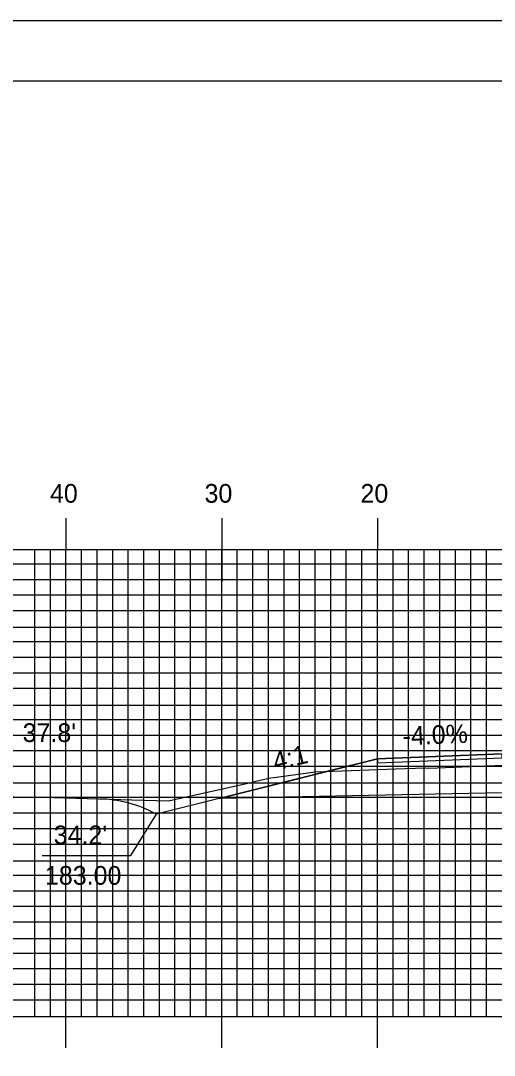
# Model space of a CAD drawing. Extents: x 1823966 to 1824309, y 442591 to 442811.
# Drawn here: x 1824088.9 to 1824119.3, y 442744.1 to 442810.5 of the extents above; entities that cross this region are included whole.
import ezdxf

# ---------------------------------------------------------------- set-up
doc = ezdxf.new("R2010")
doc.units = 0
for name, color, linetype in [('ANNOTATION', 7, 'Continuous'), ('BORDER', 7, 'Continuous'), ('D_Roadway_Centerline', 7, 'Continuous'), ('D_Roadway_Edge_Shoulder', 7, 'Continuous'), ('D_Roadway_SlopeLines', 7, 'Continuous'), ('D_Roadway_SubGrade', 7, 'Continuous'), ('D_Text_Standard', 7, 'Continuous'), ('H_V ANNOTATION', 7, 'Continuous'), ('MAJOR', 7, 'Continuous'), ('MINOR', 7, 'Continuous'), ('PLOT BOUNDARY', 7, 'Continuous'), ('S_Roadway_Centerline', 7, 'Continuous')]:
    doc.layers.add(name, color=color, linetype=linetype)

msp = doc.modelspace()

# ---------------------------------------------------------------- linework, layer by layer
at = {"layer": 'ANNOTATION'}
msp.add_lwpolyline([(1824090.301, 442756.925), (1824095.992, 442756.925), (1824097.632, 442759.588)], dxfattribs=at)
at = {"layer": 'BORDER'}
msp.add_lwpolyline([(1823982.222, 442596.665), (1824302.222, 442596.665), (1824302.222, 442806.665), (1823982.222, 442806.665)], close=True, dxfattribs=at)
at = {"layer": 'D_Roadway_Centerline'}
msp.add_lwpolyline([(1824101.648, 442760.592), (1824108.628, 442762.337), (1824111.822, 442763.135), (1824119.822, 442763.455), (1824131.822, 442763.695), (1824143.822, 442763.455), (1824151.822, 442763.135), (1824157.822, 442763.255), (1824158.422, 442763.301), (1824167.853, 442762.587), (1824172.409, 442763.689), (1824176.965, 442764.792), (1824176.965, 442764.792), (1824178.215, 442765.061), (1824179.465, 442765.188)], dxfattribs=at)
at = {"layer": 'D_Roadway_Edge_Shoulder'}
msp.add_lwpolyline([(1824119.822, 442763.455), (1824111.822, 442763.135), (1824111.822, 442762.885), (1824119.822, 442763.205)], close=True, dxfattribs=at)
at = {"layer": 'D_Roadway_SlopeLines'}
for p, q in [((1824111.822, 442763.135), (1824097.632, 442759.588)), ((1824097.632, 442759.588), (1824097.366, 442759.72))]:
    msp.add_line(p, q, dxfattribs=at)
msp.add_lwpolyline([(1824111.822, 442763.135), (1824108.628, 442762.337)], dxfattribs=at)
msp.add_arc((1824093.788, 442752.565), 8, 63.43495, 88.37605, dxfattribs=at)
at = {"layer": 'D_Roadway_SubGrade'}
msp.add_lwpolyline([(1824119.822, 442760.955), (1824101.648, 442760.592), (1824111.822, 442763.135), (1824111.822, 442762.885), (1824119.822, 442763.205), (1824131.822, 442763.445), (1824143.822, 442763.205), (1824151.822, 442762.885), (1824151.822, 442763.135), (1824151.822, 442760.635), (1824143.822, 442760.955), (1824131.822, 442761.195)], close=True, dxfattribs=at)
at = {"layer": 'MAJOR'}
for p, q in [((1824091.822, 442778.592), (1824091.822, 442776.588)), ((1824101.822, 442778.592), (1824101.822, 442776.588)), ((1824111.822, 442778.592), (1824111.822, 442776.588)), ((1823991.822, 442776.588), (1824271.822, 442776.588)), ((1824091.822, 442746.588), (1824091.822, 442776.588)), ((1824101.822, 442746.588), (1824101.822, 442776.588)), ((1824111.822, 442746.588), (1824111.822, 442776.588)), ((1824101.822, 442776.514), (1824101.822, 442774.51)), ((1823991.822, 442771.588), (1824271.822, 442771.588)), ((1823991.822, 442766.588), (1824271.822, 442766.588)), ((1823991.822, 442761.588), (1824271.822, 442761.588)), ((1823991.822, 442756.588), (1824271.822, 442756.588)), ((1823991.822, 442751.588), (1824271.822, 442751.588)), ((1823991.822, 442746.588), (1824271.822, 442746.588)), ((1823991.822, 442746.588), (1824271.822, 442746.588)), ((1824091.822, 442744.584), (1824091.822, 442746.588)), ((1824101.822, 442744.584), (1824101.822, 442746.588)), ((1824111.822, 442744.584), (1824111.822, 442746.588))]:
    msp.add_line(p, q, dxfattribs=at)
at = {"layer": 'MINOR'}
for p, q in [((1824089.822, 442746.588), (1824089.822, 442776.588)), ((1824090.822, 442746.588), (1824090.822, 442776.588)), ((1824092.822, 442746.588), (1824092.822, 442776.588)), ((1824093.822, 442746.588), (1824093.822, 442776.588)), ((1824094.822, 442746.588), (1824094.822, 442776.588)), ((1824095.822, 442746.588), (1824095.822, 442776.588)), ((1824096.822, 442746.588), (1824096.822, 442776.588)), ((1824097.822, 442746.588), (1824097.822, 442776.588)), ((1824098.822, 442746.588), (1824098.822, 442776.588)), ((1824099.822, 442746.588), (1824099.822, 442776.588)), ((1824100.822, 442746.588), (1824100.822, 442776.588)), ((1824102.822, 442746.588), (1824102.822, 442776.588)), ((1824103.822, 442746.588), (1824103.822, 442776.588)), ((1824104.822, 442746.588), (1824104.822, 442776.588)), ((1824105.822, 442746.588), (1824105.822, 442776.588)), ((1824106.822, 442746.588), (1824106.822, 442776.588)), ((1824107.822, 442746.588), (1824107.822, 442776.588)), ((1824108.822, 442746.588), (1824108.822, 442776.588)), ((1824109.822, 442746.588), (1824109.822, 442776.588)), ((1824110.822, 442746.588), (1824110.822, 442776.588)), ((1824112.822, 442746.588), (1824112.822, 442776.588)), ((1824113.822, 442746.588), (1824113.822, 442776.588)), ((1824114.822, 442746.588), (1824114.822, 442776.588)), ((1824115.822, 442746.588), (1824115.822, 442776.588)), ((1824116.822, 442746.588), (1824116.822, 442776.588)), ((1824117.822, 442746.588), (1824117.822, 442776.588)), ((1824118.822, 442746.588), (1824118.822, 442776.588)), ((1823991.822, 442775.665), (1824271.822, 442775.665)), ((1823991.822, 442774.665), (1824271.822, 442774.665)), ((1823991.822, 442773.665), (1824271.822, 442773.665)), ((1823991.822, 442772.665), (1824271.822, 442772.665)), ((1823991.822, 442770.665), (1824271.822, 442770.665)), ((1823991.822, 442769.665), (1824271.822, 442769.665)), ((1823991.822, 442768.665), (1824271.822, 442768.665)), ((1823991.822, 442767.665), (1824271.822, 442767.665)), ((1823991.822, 442765.665), (1824271.822, 442765.665)), ((1823991.822, 442764.665), (1824271.822, 442764.665)), ((1823991.822, 442763.665), (1824271.822, 442763.665)), ((1823991.822, 442762.665), (1824271.822, 442762.665)), ((1823991.822, 442760.665), (1824271.822, 442760.665)), ((1823991.822, 442759.665), (1824271.822, 442759.665)), ((1823991.822, 442758.665), (1824271.822, 442758.665)), ((1823991.822, 442757.665), (1824271.822, 442757.665)), ((1823991.822, 442755.665), (1824271.822, 442755.665)), ((1823991.822, 442754.665), (1824271.822, 442754.665)), ((1823991.822, 442753.665), (1824271.822, 442753.665)), ((1823991.822, 442752.665), (1824271.822, 442752.665)), ((1823991.822, 442750.665), (1824271.822, 442750.665)), ((1823991.822, 442749.665), (1824271.822, 442749.665)), ((1823991.822, 442748.665), (1824271.822, 442748.665)), ((1823991.822, 442747.665), (1824271.822, 442747.665))]:
    msp.add_line(p, q, dxfattribs=at)
at = {"layer": 'PLOT BOUNDARY'}
msp.add_lwpolyline([(1823966.035, 442590.547), (1824306.035, 442590.547), (1824306.035, 442810.547), (1823966.035, 442810.547)], close=True, dxfattribs=at)
at = {"layer": 'S_Roadway_Centerline'}
msp.add_lwpolyline([(1824085.878, 442760.732), (1824091.034, 442760.646), (1824096.046, 442760.504), (1824098.405, 442760.449), (1824103.505, 442761.574), (1824104.104, 442761.718), (1824104.978, 442761.92), (1824105.478, 442761.986), (1824107.815, 442762.306), (1824113.004, 442762.502), (1824114.883, 442762.563), (1824115.129, 442762.531), (1824123.073, 442762.855)], dxfattribs=at)

# ---------------------------------------------------------------- texts
at = {"layer": 'ANNOTATION'}
for s, rotation, p in [('-4.0%', 2.29061, (1824113.454, 442764.002)), ('4:1', 14.03624, (1824105.27, 442762.359))]:
    msp.add_text(s, height=1.2, rotation=rotation, dxfattribs=at).set_placement(p)
for s, p in [("34.2'", (1824091.036, 442757.651)), ('183.00', (1824090.473, 442755.051))]:
    msp.add_text(s, height=1.2, dxfattribs=at).set_placement(p)
at = {"layer": 'D_Text_Standard'}
msp.add_text("37.8'", height=1.2, dxfattribs=at).set_placement((1824089.039, 442764.218))
at = {"layer": 'H_V ANNOTATION'}
for s, p in [('40', (1824090.794, 442779.588)), ('30', (1824100.719, 442779.588)), ('20', (1824110.73, 442779.588))]:
    msp.add_text(s, height=1.2, dxfattribs=at).set_placement(p)

doc.saveas('drawing.dxf')
